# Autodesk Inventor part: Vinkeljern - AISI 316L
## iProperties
Company: Cad-Q A/S
Author: Administrator
Shininess: 25.0
PropertySet Name: _Private Model Information
Created: 2001-02
Part Number: Vinkeljern - AISI 316L
Material: Stainless Steel, AISI 316L
Document SubType Name: Modeling
Designer: Administrator
Control State: 0
Master: False
Checked Out: False
PropertySet Name: Design Tracking Control
Density: 8.03
Volumn: 1.3093138785576415
Area: 11.68986722862693
PropertySet Name: Model Information
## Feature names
1. Extrusion1
2. Fillet1
